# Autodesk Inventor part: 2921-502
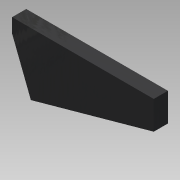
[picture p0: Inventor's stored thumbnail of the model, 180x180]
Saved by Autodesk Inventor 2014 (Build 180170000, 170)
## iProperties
Company: NHTSA/VRTC
Created: 2011-11
Part Number: 2921-502
Material: EVA Foam
Document SubType Name: Modeling
Designer: Mike Vanvoorhis
Density: 0.941117 g/cm^3
Project: CHILD SIDE IMPACT SLED
Description: Crosslinked Polyethylene Closed Cell (XPLE) Foam 4 PCF, 63.5 (2.5") x 635 mm (25.0") x 280 mm (11.0")
Mass: 7267.27 g
Surface Area: 3456.31 cm^2
Volume: 7721.96 cm^3
Appearance: Dark Gray
Author: Dave Walker
Title: IMPACTOR ARMREST FOAM
Subject: Child Side Impact Sled
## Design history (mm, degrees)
sketch "Sketch2"
  geometry: L1 (-635, 0)-(0, 0); L2 (0, 0)-(0, -127); L3 (0, -127)-(-550.715, -279.727); L4 (-550.715, -279.727)-(-635, -63.5); L5 (-635, -63.5)-(-635, 0); 1 further point
  constraints: 10 end point, 1 coincident, 1 horizontal, 1 parallel
  dimensions: "d0" = 635 distance of L1.start L1.end; "d2" = 127 distance of L1.end L2.end; "d3" = 571.5 distance of L2.end L3.end; "d5" = 63.5 distance of L4.end L1.start; "d9" = 105.5 deg angle of L2 L3; "d10" = 90 deg angle of L2 L1
extrude "Extrusion1" new body sketch "Sketch2" distance "d7" = 63.5; taper "d8" = 0 deg
body "Solid2"
